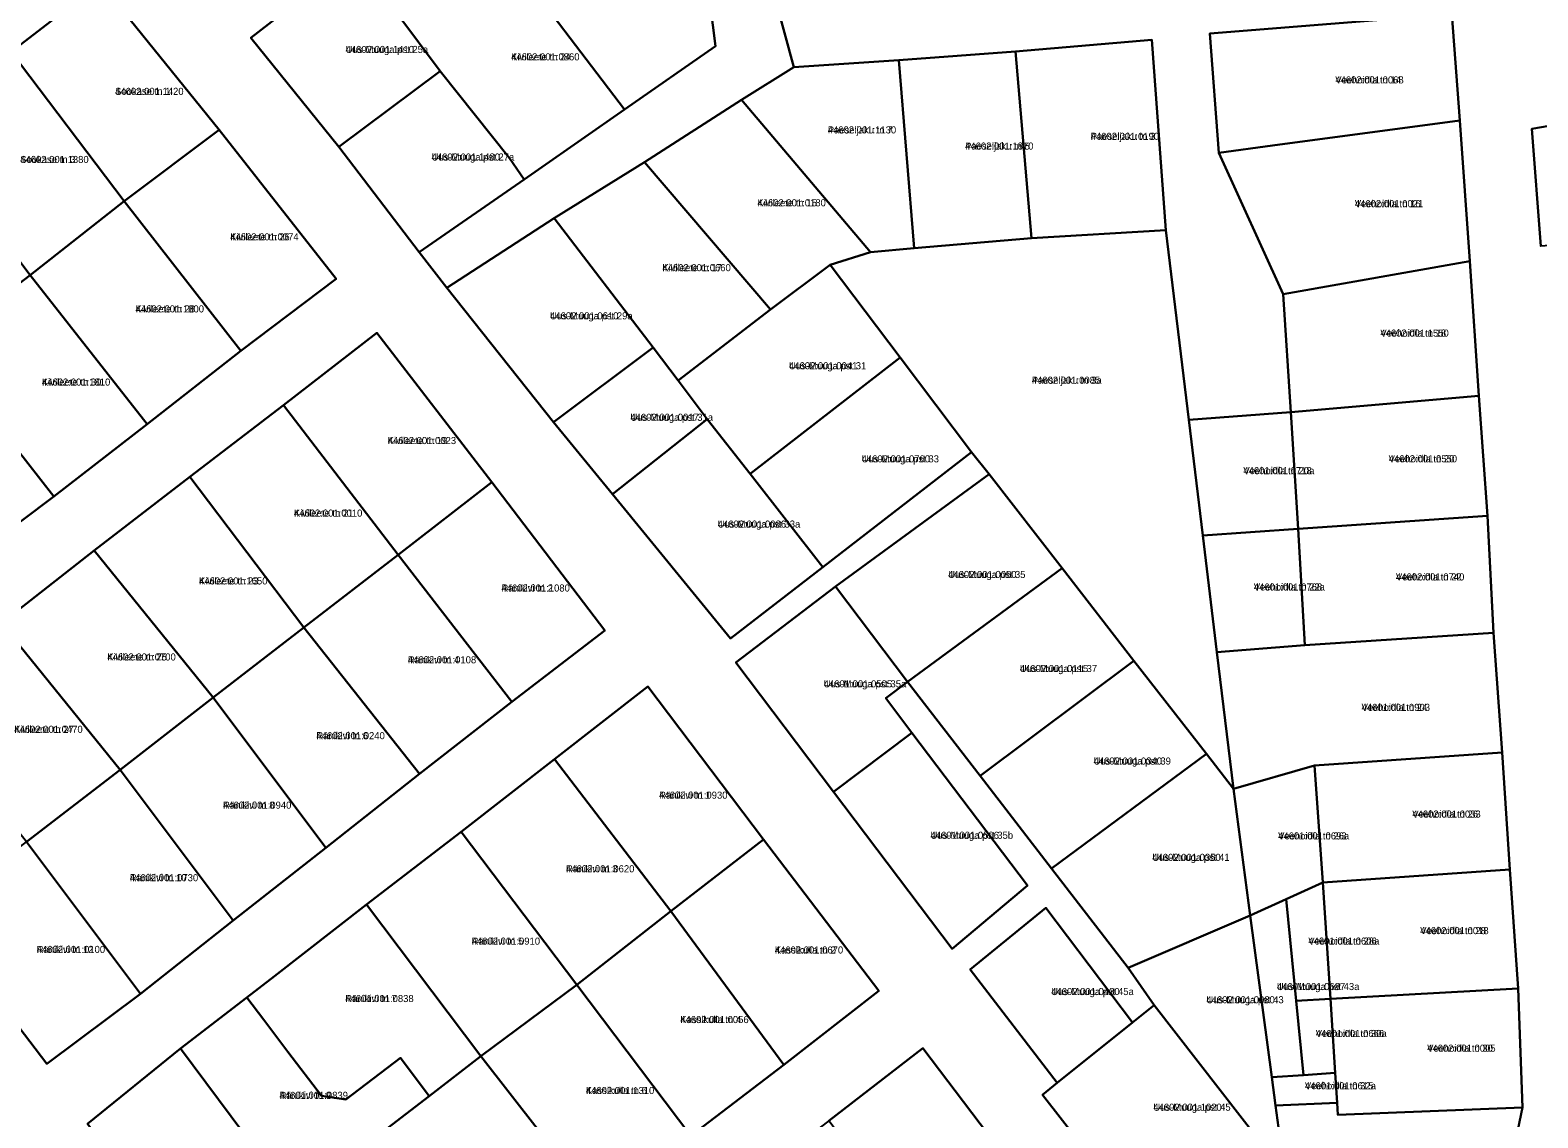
# Model space of a CAD drawing. Extents: x 551843 to 558501, y 6589003 to 6595718.
# Drawn here: x 554378.5 to 554698.1, y 6593446 to 6593676.5 of the extents above; entities that cross this region are included whole.
import ezdxf

# ---------------------------------------------------------------- set-up
doc = ezdxf.new("R2010")
doc.units = 0
for name, color, linetype in [('L_AADRESS', 7, 'Continuous'), ('PIIR', 7, 'Continuous'), ('TUNNUS', 7, 'Continuous')]:
    doc.layers.add(name, color=color, linetype=linetype)

msp = doc.modelspace()

# ---------------------------------------------------------------- linework, layer by layer
at = {"layer": 'PIIR'}
for points in [[(554360.94, 6593757.39), (554378.58, 6593734.45), (554400.84, 6593751.11), (554406.54, 6593744.22), (554402.31, 6593741.15), (554400.69, 6593742.46), (554399.02, 6593742.6), (554397.63, 6593742.2), (554381.75, 6593729.61), (554401.71, 6593704.92), (554423.97, 6593721.87), (554426.83, 6593718.04), (554404.62, 6593701.01), (554393.47, 6593686.49), (554374.48, 6593671.9)], [(554536.44, 6593683.26), (554540.41, 6593668.61), (554529.28, 6593661.67), (554508.71, 6593648.49), (554489.56, 6593636.61), (554466.82, 6593621.85), (554460.95, 6593629.42), (554483.25, 6593644.85), (554504.48, 6593659.62), (554523.76, 6593673.04), (554520.95, 6593695.37)], [(554447.47, 6593692.07), (554425.32, 6593674.81), (554443.96, 6593651.76), (554460.95, 6593629.42), (554466.82, 6593621.85), (554489.46, 6593593.38), (554501.95, 6593578.12), (554526.97, 6593547.55), (554546.53, 6593562.68), (554578.01, 6593587.02), (554581.75, 6593582.39), (554549.23, 6593558.56), (554528.06, 6593542.5), (554548.76, 6593515.05), (554573.96, 6593481.83), (554589.94, 6593495.22), (554565.37, 6593527.58), (554559.89, 6593534.89), (554564.46, 6593538.37), (554579.88, 6593518.46), (554594.98, 6593498.84), (554611.24, 6593477.76), (554616.78, 6593469.9), (554612.14, 6593466.16), (554593.82, 6593490.46), (554577.73, 6593477.4), (554596.18, 6593453.39), (554593.05, 6593450.89), (554614.3, 6593423.64)], [(554363.47, 6593562.61), (554383.58, 6593577.63), (554403.33, 6593592.97), (554423.2, 6593608.49), (554443.37, 6593623.79), (554418.61, 6593655.37), (554393.47, 6593686.49)], [(554693.84, 6593443.43), (554694.84, 6593448.21), (554693.87, 6593473.39), (554692.11, 6593498.6), (554690.52, 6593523.37), (554688.66, 6593548.76), (554687.37, 6593573.55), (554685.53, 6593599), (554683.65, 6593627.54), (554681.53, 6593657.34), (554679.87, 6593679.88), (554628.53, 6593675.78), (554630.45, 6593650.48), (554644.11, 6593620.55), (554645.69, 6593595.52), (554624.07, 6593593.88), (554619.2, 6593634.09), (554616.29, 6593674.45), (554587.37, 6593671.94), (554562.65, 6593670.1), (554540.41, 6593668.61), (554536.44, 6593683.26)], [(554736.28, 6593662.38), (554696.76, 6593655.59), (554698.7, 6593630.7)]]:
    msp.add_lwpolyline(points, dxfattribs=at)
for points in [[(554520.95, 6593695.37), (554523.76, 6593673.04), (554504.48, 6593659.62), (554478.97, 6593693.24)], [(554447.47, 6593692.07), (554456.45, 6593679.76), (554465.43, 6593667.78), (554443.96, 6593651.76), (554425.32, 6593674.81)], [(554478.97, 6593693.24), (554504.48, 6593659.62), (554483.25, 6593644.85), (554480.14, 6593649.32), (554465.43, 6593667.78), (554456.45, 6593679.76)], [(554393.47, 6593686.49), (554418.61, 6593655.37), (554398.48, 6593640.26), (554374.48, 6593671.9)], [(554628.53, 6593675.78), (554679.87, 6593679.88), (554681.53, 6593657.34), (554641.8, 6593652.02), (554630.45, 6593650.48)], [(554374.48, 6593671.9), (554398.48, 6593640.26), (554378.53, 6593624.54), (554354.38, 6593656.38)], [(554562.65, 6593670.1), (554587.37, 6593671.94), (554590.72, 6593632.36), (554565.87, 6593630.26)], [(554616.29, 6593674.45), (554619.2, 6593634.09), (554590.72, 6593632.36), (554587.37, 6593671.94)], [(554540.41, 6593668.61), (554562.65, 6593670.1), (554565.87, 6593630.26), (554556.6, 6593629.42), (554529.28, 6593661.67)], [(554465.43, 6593667.78), (554480.14, 6593649.32), (554483.25, 6593644.85), (554460.95, 6593629.42), (554443.96, 6593651.76)], [(554696.76, 6593655.59), (554736.28, 6593662.38), (554738.52, 6593633.7), (554698.7, 6593630.7)], [(554556.6, 6593629.42), (554548.06, 6593626.74), (554535.47, 6593617.31), (554508.71, 6593648.49), (554529.28, 6593661.67)], [(554354.38, 6593656.38), (554378.53, 6593624.54), (554358.69, 6593609.46), (554334.49, 6593641.06)], [(554418.61, 6593655.37), (554443.37, 6593623.79), (554423.2, 6593608.49), (554398.48, 6593640.26)], [(554630.45, 6593650.48), (554641.8, 6593652.02), (554681.53, 6593657.34), (554683.65, 6593627.54), (554644.11, 6593620.55)], [(554508.71, 6593648.49), (554535.47, 6593617.31), (554515.9, 6593602.23), (554510.6, 6593609.25), (554489.56, 6593636.61)], [(554398.48, 6593640.26), (554423.2, 6593608.49), (554403.33, 6593592.97), (554378.53, 6593624.54)], [(554510.6, 6593609.25), (554489.46, 6593593.38), (554466.82, 6593621.85), (554489.56, 6593636.61)], [(554548.06, 6593626.74), (554556.6, 6593629.42), (554565.87, 6593630.26), (554590.72, 6593632.36), (554619.2, 6593634.09), (554624.07, 6593593.88), (554627.04, 6593569.41), (554630.03, 6593544.68), (554633.56, 6593515.68), (554627.82, 6593523.11), (554612.46, 6593542.85), (554597.23, 6593562.43), (554581.75, 6593582.39), (554578.01, 6593587.02), (554562.91, 6593607.08)], [(554562.91, 6593607.08), (554531.15, 6593582.48), (554522.04, 6593594.01), (554515.9, 6593602.23), (554535.47, 6593617.31), (554548.06, 6593626.74)], [(554645.69, 6593595.52), (554644.11, 6593620.55), (554683.65, 6593627.54), (554685.53, 6593599)], [(554378.53, 6593624.54), (554403.33, 6593592.97), (554383.58, 6593577.63), (554358.69, 6593609.46)], [(554476.4, 6593580.68), (554452, 6593612.33), (554432.2, 6593597.02), (554412.35, 6593581.81), (554392.11, 6593566.18), (554372.43, 6593550.81), (554352.76, 6593535.68), (554333.11, 6593520.38), (554357.89, 6593489.06), (554382.05, 6593457.43), (554401.92, 6593472.27), (554421.53, 6593487.82), (554441.21, 6593503.19), (554461.03, 6593518.87), (554480.6, 6593534.15), (554500.31, 6593549.23)], [(554452, 6593612.33), (554476.4, 6593580.68), (554456.51, 6593565.29), (554432.2, 6593597.02)], [(554358.69, 6593609.46), (554383.58, 6593577.63), (554363.47, 6593562.61), (554338.52, 6593594.03)], [(554515.9, 6593602.23), (554522.04, 6593594.01), (554501.95, 6593578.12), (554489.46, 6593593.38), (554510.6, 6593609.25)], [(554562.91, 6593607.08), (554578.01, 6593587.02), (554546.53, 6593562.68), (554531.15, 6593582.48)], [(554647.25, 6593570.8), (554645.69, 6593595.52), (554685.53, 6593599), (554687.37, 6593573.55)], [(554432.2, 6593597.02), (554456.51, 6593565.29), (554436.52, 6593549.92), (554412.35, 6593581.81)], [(554627.04, 6593569.41), (554624.07, 6593593.88), (554645.69, 6593595.52), (554647.25, 6593570.8)], [(554501.95, 6593578.12), (554522.04, 6593594.01), (554531.15, 6593582.48), (554546.53, 6593562.68), (554526.97, 6593547.55)], [(554581.75, 6593582.39), (554597.23, 6593562.43), (554564.46, 6593538.37), (554549.23, 6593558.56)], [(554412.35, 6593581.81), (554436.52, 6593549.92), (554417.34, 6593535.08), (554392.11, 6593566.18)], [(554476.4, 6593580.68), (554500.31, 6593549.23), (554480.6, 6593534.15), (554456.51, 6593565.29)], [(554648.7, 6593546.16), (554647.25, 6593570.8), (554687.37, 6593573.55), (554688.66, 6593548.76)], [(554630.03, 6593544.68), (554627.04, 6593569.41), (554647.25, 6593570.8), (554648.7, 6593546.16)], [(554392.11, 6593566.18), (554417.34, 6593535.08), (554397.57, 6593519.71), (554372.43, 6593550.81)], [(554436.52, 6593549.92), (554456.51, 6593565.29), (554480.6, 6593534.15), (554461.02, 6593518.85)], [(554564.46, 6593538.37), (554597.23, 6593562.43), (554612.46, 6593542.85), (554579.88, 6593518.46)], [(554565.37, 6593527.58), (554548.76, 6593515.05), (554528.06, 6593542.5), (554549.23, 6593558.56), (554564.46, 6593538.37), (554559.89, 6593534.89)], [(554372.43, 6593550.81), (554397.57, 6593519.71), (554377.75, 6593504.49), (554352.76, 6593535.68)], [(554461.03, 6593518.87), (554441.21, 6593503.19), (554417.34, 6593535.08), (554436.52, 6593549.92)], [(554633.56, 6593515.68), (554630.03, 6593544.68), (554648.7, 6593546.16), (554688.66, 6593548.76), (554690.52, 6593523.37), (554650.72, 6593520.63)], [(554579.88, 6593518.46), (554612.46, 6593542.85), (554627.82, 6593523.11), (554594.98, 6593498.84)], [(554558.39, 6593472.91), (554533.97, 6593504.96), (554509.47, 6593537.37), (554489.67, 6593522), (554469.89, 6593506.62), (554449.82, 6593491.18), (554430.33, 6593476.01), (554424.48, 6593471.49), (554410.37, 6593460.67), (554390.71, 6593444.69), (554414.79, 6593413.03), (554438.86, 6593381.38), (554458.73, 6593396.56), (554478.79, 6593411.86), (554498.88, 6593427.13), (554518.54, 6593442.19), (554538.24, 6593457.19)], [(554533.97, 6593504.96), (554514.29, 6593489.75), (554489.67, 6593522), (554509.47, 6593537.37)], [(554417.34, 6593535.08), (554441.21, 6593503.19), (554421.53, 6593487.82), (554397.57, 6593519.71)], [(554589.94, 6593495.22), (554573.96, 6593481.83), (554548.76, 6593515.05), (554565.37, 6593527.58)], [(554489.67, 6593522), (554514.29, 6593489.75), (554494.38, 6593474.18), (554469.89, 6593506.62)], [(554594.98, 6593498.84), (554627.82, 6593523.11), (554633.56, 6593515.68), (554637.08, 6593488.85), (554611.24, 6593477.76)], [(554650.72, 6593520.63), (554690.52, 6593523.37), (554692.11, 6593498.6), (554652.49, 6593495.84)], [(554397.57, 6593519.71), (554421.53, 6593487.82), (554401.92, 6593472.27), (554377.75, 6593504.49)], [(554652.49, 6593495.84), (554644.7, 6593492.3), (554637.08, 6593488.85), (554633.56, 6593515.68), (554650.72, 6593520.63)], [(554494.38, 6593474.18), (554474.07, 6593459.05), (554449.82, 6593491.18), (554469.89, 6593506.62)], [(554377.75, 6593504.49), (554401.92, 6593472.27), (554382.05, 6593457.43), (554357.89, 6593489.06)], [(554514.29, 6593489.75), (554533.97, 6593504.96), (554558.39, 6593472.91), (554538.24, 6593457.19)], [(554644.7, 6593492.3), (554652.49, 6593495.84), (554654.13, 6593471.22), (554646.85, 6593470.81)], [(554692.11, 6593498.6), (554693.87, 6593473.39), (554654.13, 6593471.22), (554652.49, 6593495.84)], [(554428.06, 6593466.74), (554424.48, 6593471.49), (554430.33, 6593476.01), (554449.82, 6593491.18), (554474.07, 6593459.05), (554463.12, 6593450.6), (554457.04, 6593458.74), (554445.4, 6593449.86), (554440.31, 6593450.67), (554433.16, 6593460)], [(554494.38, 6593474.18), (554514.29, 6593489.75), (554538.24, 6593457.19), (554518.54, 6593442.19)], [(554593.82, 6593490.46), (554612.14, 6593466.16), (554596.18, 6593453.39), (554577.73, 6593477.4)], [(554641.71, 6593454.64), (554637.08, 6593488.85), (554644.7, 6593492.3), (554646.85, 6593470.81), (554648.42, 6593455.02)], [(554644.4, 6593434.65), (554640.09, 6593439.84), (554616.78, 6593469.9), (554611.24, 6593477.76), (554637.08, 6593488.85), (554641.71, 6593454.64), (554642.5, 6593448.58)], [(554494.38, 6593474.18), (554518.54, 6593442.19), (554498.88, 6593427.13), (554474.07, 6593459.05)], [(554693.87, 6593473.39), (554694.84, 6593448.21), (554655.7, 6593446.61), (554655.54, 6593449.15), (554655.13, 6593455.5), (554654.13, 6593471.22)], [(554434.36, 6593428.54), (554410.37, 6593460.67), (554424.48, 6593471.49), (554428.06, 6593466.74), (554433.16, 6593460), (554440.31, 6593450.67), (554445.4, 6593449.86), (554457.04, 6593458.74), (554463.12, 6593450.6), (554454.26, 6593443.78)], [(554646.85, 6593470.81), (554654.13, 6593471.22), (554655.13, 6593455.5), (554648.42, 6593455.02)], [(554640.09, 6593439.84), (554625.24, 6593431.4), (554614.3, 6593423.64), (554593.05, 6593450.89), (554596.18, 6593453.39), (554616.78, 6593469.9)], [(554434.36, 6593428.54), (554414.79, 6593413.03), (554390.71, 6593444.69), (554410.37, 6593460.67)], [(554592.06, 6593428.7), (554567.74, 6593460.75), (554547.83, 6593445.37), (554527.95, 6593430.21), (554508.09, 6593414.78), (554488.08, 6593399.67), (554467.99, 6593384.32), (554448.06, 6593369.09), (554472.14, 6593336.71), (554495.13, 6593304.83), (554516.12, 6593320.8), (554536.02, 6593335.58), (554555.87, 6593350.77), (554576, 6593366.27), (554596.28, 6593381.66), (554616.22, 6593396.76)], [(554571.97, 6593413.39), (554547.83, 6593445.37), (554567.74, 6593460.75), (554592.06, 6593428.7)], [(554474.07, 6593459.05), (554498.88, 6593427.13), (554478.79, 6593411.86), (554454.26, 6593443.78), (554463.12, 6593450.6)], [(554642.5, 6593448.58), (554641.71, 6593454.64), (554648.42, 6593455.02), (554655.13, 6593455.5), (554655.54, 6593449.15)], [(554642.5, 6593448.58), (554655.54, 6593449.15), (554655.7, 6593446.61), (554694.84, 6593448.21), (554693.84, 6593443.43), (554652, 6593410.62), (554644.4, 6593434.65)]]:
    msp.add_lwpolyline(points, close=True, dxfattribs=at)

# ---------------------------------------------------------------- texts
at = {"layer": 'L_AADRESS'}
for s, p in [('Uus-Muuga pst 25a', (554445.38, 6593671.63)), ('Kivileete tn 24', (554480.46, 6593670.06)), ('Veehoidla tn 14', (554655.14, 6593665.18)), ('Sookase tn 1', (554396.54, 6593662.75)), ('Paeseljaku tn 7', (554547.57, 6593654.58)), ('Paeseljaku tn 5', (554576.68, 6593651.16)), ('Paeseljaku tn 3', (554603.29, 6593653.22)), ('Sookase tn 3', (554376.43, 6593648.32)), ('Uus-Muuga pst 27a', (554463.61, 6593648.84)), ('Kivileete tn 15', (554532.66, 6593639.14)), ('Veehoidla tn 16', (554659.28, 6593638.95)), ('Kivileete tn 26', (554420.92, 6593631.92)), ('Kivileete tn 17', (554512.52, 6593625.39)), ('Kivileete tn 28', (554400.87, 6593616.65)), ('Uus-Muuga pst 29a', (554488.71, 6593615.19)), ('Veehoidla tn 18', (554664.69, 6593611.53)), ('Uus-Muuga pst 31', (554539.35, 6593604.61)), ('Kivileete tn 30', (554381.01, 6593601.15)), ('Paeseljaku tn 3a', (554590.81, 6593601.54)), ('Uus-Muuga pst 31a', (554505.75, 6593593.69)), ('Kivileete tn 19', (554454.3, 6593588.76)), ('Uus-Muuga pst 33', (554554.75, 6593584.88)), ('Veehoidla tn 20', (554666.45, 6593584.9)), ('Veehoidla tn 20a', (554635.66, 6593582.38)), ('Kivileete tn 21', (554434.43, 6593573.39)), ('Uus-Muuga pst 33a', (554524.24, 6593571.06)), ('Kivileete tn 23', (554414.32, 6593559.01)), ('Uus-Muuga pst 35', (554573.08, 6593560.38)), ('Veehoidla tn 22', (554667.99, 6593559.86)), ('Ränikivi tn 2', (554478.41, 6593557.51)), ('Veehoidla tn 22a', (554637.87, 6593557.73)), ('Kivileete tn 25', (554394.89, 6593542.9)), ('Ränikivi tn 4', (554458.56, 6593542.3)), ('Uus-Muuga pst 37', (554588.27, 6593540.45)), ('Uus-Muuga pst 35a', (554546.71, 6593537.21)), ('Veehoidla tn 24', (554660.71, 6593532.22)), ('Kivileete tn 27', (554375.16, 6593527.57)), ('Ränikivi tn 6', (554439.19, 6593526.22)), ('Uus-Muuga pst 39', (554603.91, 6593520.85)), ('Ränikivi tn 1', (554511.82, 6593513.62)), ('Ränikivi tn 8', (554419.39, 6593511.5)), ('Veehoidla tn 26', (554671.46, 6593509.61)), ('Uus-Muuga pst 35b', (554569.35, 6593505.12)), ('Veehoidla tn 26a', (554643.03, 6593504.98)), ('Uus-Muuga pst 41', (554616.35, 6593500.44)), ('Ränikivi tn 3', (554492.09, 6593498.02)), ('Ränikivi tn 10', (554399.64, 6593496.13)), ('Veehoidla tn 28', (554673.14, 6593484.91)), ('Ränikivi tn 5', (554472.1, 6593482.68)), ('Veehoidla tn 28a', (554649.42, 6593482.7)), ('Ränikivi tn 12', (554379.91, 6593480.93)), ('Kassikulla tn 2', (554536.34, 6593480.81)), ('Uus-Muuga pst 45a', (554594.93, 6593472)), ('Uus-Muuga pst 43a', (554642.75, 6593473.06)), ('Ränikivi tn 7', (554445.31, 6593470.52)), ('Uus-Muuga pst 43', (554627.82, 6593470.27)), ('Kassikulla tn 4', (554516.31, 6593466.07)), ('Veehoidla tn 30a', (554650.99, 6593463.12)), ('Veehoidla tn 30', (554674.61, 6593460)), ('Ränikivi tn 9', (554431.38, 6593450.01)), ('Kassikulla tn 6', (554496.3, 6593451.04)), ('Veehoidla tn 32a', (554648.7, 6593452.04)), ('Uus-Muuga pst 45', (554616.57, 6593447.49))]:
    msp.add_text(s, height=1.5, dxfattribs=at).set_placement(p)
at = {"layer": 'TUNNUS'}
for s, p in [('44602:001:1410', (554445.38, 6593671.63)), ('44602:001:0860', (554480.46, 6593670.06)), ('44602:001:0068', (554655.14, 6593665.18)), ('44602:001:1420', (554396.54, 6593662.75)), ('44602:001:1130', (554547.57, 6593654.58)), ('44602:001:1870', (554576.68, 6593651.16)), ('44602:001:0190', (554603.29, 6593653.22)), ('44602:001:1380', (554376.43, 6593648.32)), ('44602:001:1480', (554463.61, 6593648.84)), ('44602:001:0180', (554532.66, 6593639.14)), ('44602:001:0021', (554659.28, 6593638.95)), ('44602:001:0074', (554420.92, 6593631.92)), ('44602:001:0660', (554512.52, 6593625.39)), ('44602:001:1800', (554400.87, 6593616.65)), ('44602:001:0610', (554488.71, 6593615.19)), ('44602:001:1550', (554664.69, 6593611.53)), ('44602:001:0041', (554539.35, 6593604.61)), ('44602:001:1810', (554381.01, 6593601.15)), ('44602:001:0085', (554590.81, 6593601.54)), ('44602:001:0017', (554505.75, 6593593.69)), ('44602:001:0023', (554454.3, 6593588.76)), ('44602:001:0760', (554554.75, 6593584.88)), ('44602:001:0550', (554666.45, 6593584.9)), ('44601:001:0718', (554635.66, 6593582.38)), ('44602:001:0010', (554434.43, 6593573.39)), ('44602:001:0086', (554524.24, 6593571.06)), ('44602:001:1650', (554414.32, 6593559.01)), ('44602:001:0050', (554573.08, 6593560.38)), ('44602:001:0740', (554667.99, 6593559.86)), ('44602:001:1080', (554478.41, 6593557.51)), ('44601:001:0768', (554637.87, 6593557.73)), ('44602:001:0700', (554394.89, 6593542.9)), ('44602:001:0108', (554458.56, 6593542.3)), ('44602:001:0115', (554588.27, 6593540.45)), ('44601:001:0505', (554546.71, 6593537.21)), ('44601:001:0903', (554660.71, 6593532.22)), ('44602:001:0470', (554375.16, 6593527.57)), ('44602:001:0240', (554439.19, 6593526.22)), ('44602:001:0340', (554603.91, 6593520.85)), ('44602:001:0930', (554511.82, 6593513.62)), ('44602:001:0940', (554419.39, 6593511.5)), ('44602:001:0033', (554671.46, 6593509.61)), ('44601:001:0506', (554569.35, 6593505.12)), ('44601:001:0693', (554643.03, 6593504.98)), ('44602:001:0350', (554616.35, 6593500.44)), ('44602:001:0620', (554492.09, 6593498.02)), ('44602:001:0730', (554399.64, 6593496.13)), ('44602:001:0018', (554673.14, 6593484.91)), ('44602:001:0910', (554472.1, 6593482.68)), ('44601:001:0606', (554649.42, 6593482.7)), ('44602:001:0100', (554379.91, 6593480.93)), ('44602:001:0670', (554536.34, 6593480.81)), ('44602:001:0430', (554594.93, 6593472)), ('44601:001:0687', (554642.75, 6593473.06)), ('44601:001:0838', (554445.31, 6593470.52)), ('44602:001:0080', (554627.82, 6593470.27)), ('44602:001:0056', (554516.31, 6593466.07)), ('44601:001:0666', (554650.99, 6593463.12)), ('44602:001:0005', (554674.61, 6593460)), ('44601:001:0839', (554431.38, 6593450.01)), ('44602:001:1310', (554496.3, 6593451.04)), ('44601:001:0615', (554648.7, 6593452.04)), ('44602:001:1020', (554616.57, 6593447.49))]:
    msp.add_text(s, height=1.5, dxfattribs=at).set_placement(p)

doc.saveas('drawing.dxf')
